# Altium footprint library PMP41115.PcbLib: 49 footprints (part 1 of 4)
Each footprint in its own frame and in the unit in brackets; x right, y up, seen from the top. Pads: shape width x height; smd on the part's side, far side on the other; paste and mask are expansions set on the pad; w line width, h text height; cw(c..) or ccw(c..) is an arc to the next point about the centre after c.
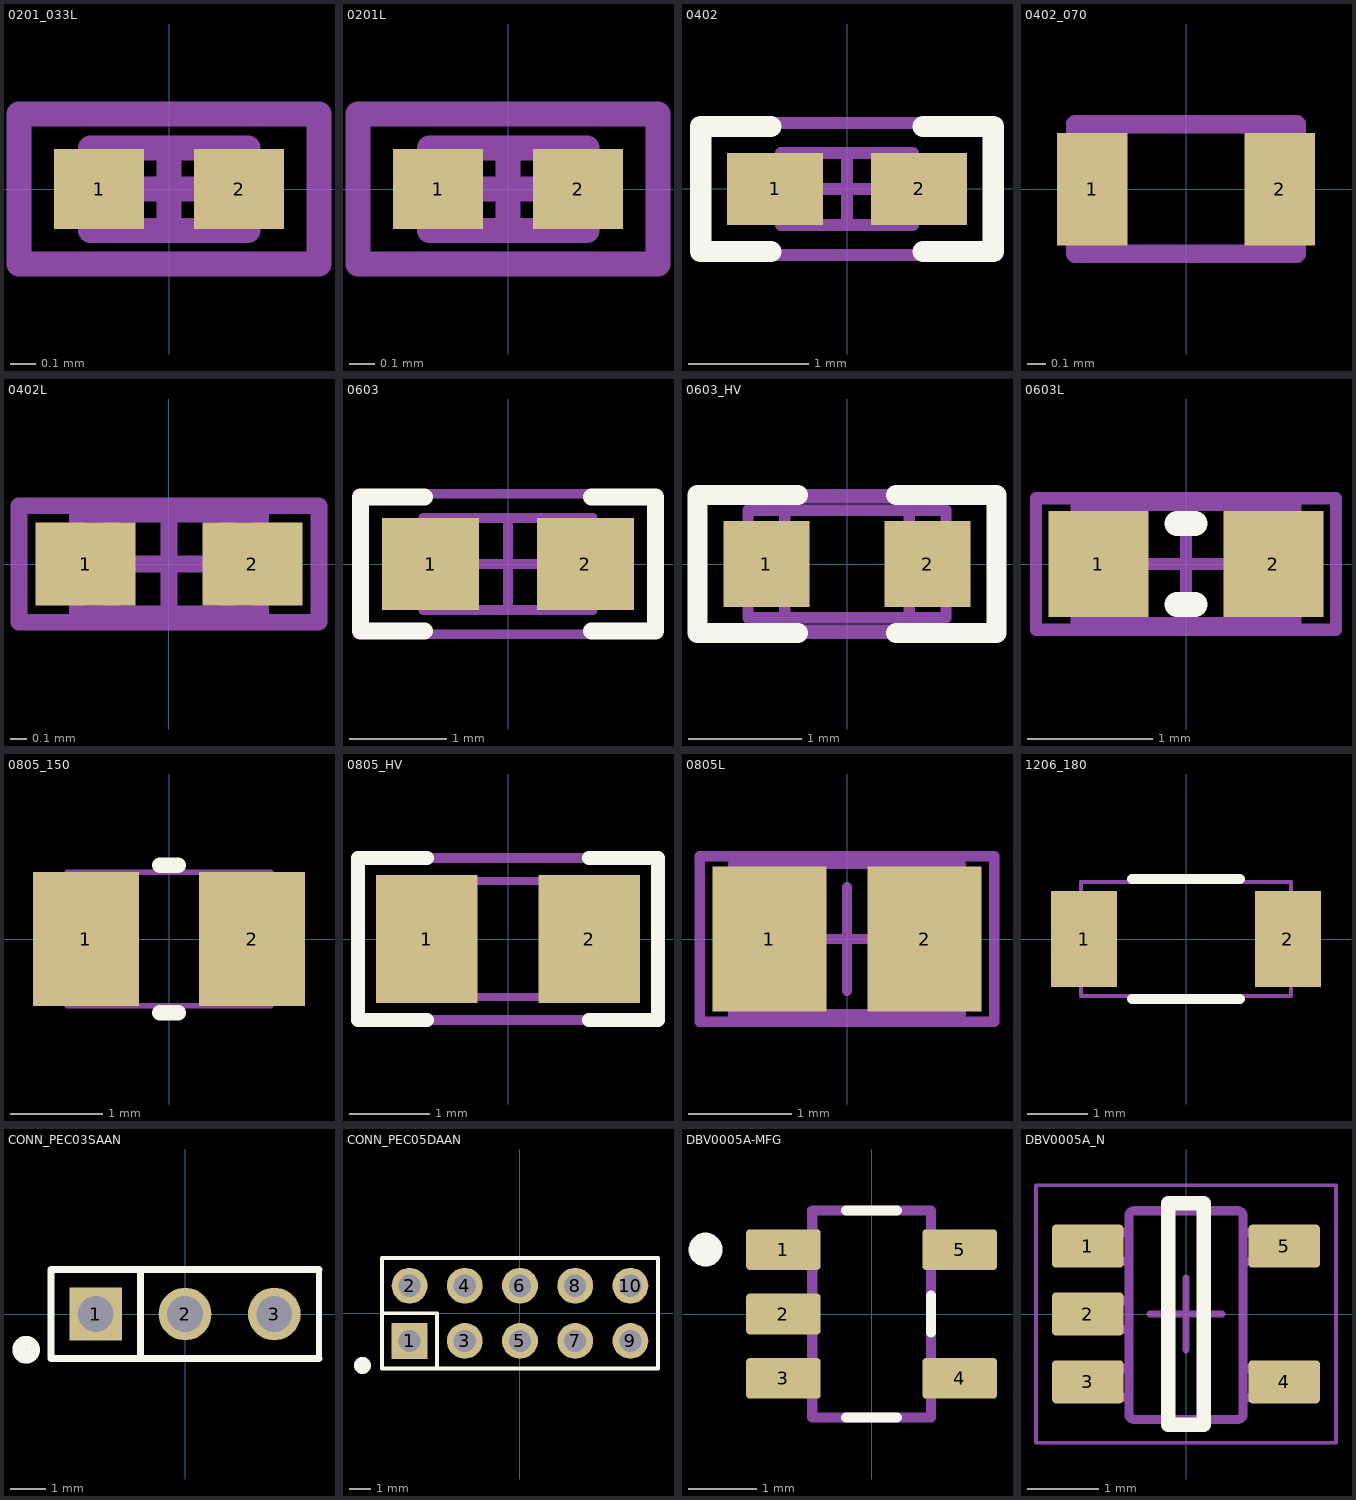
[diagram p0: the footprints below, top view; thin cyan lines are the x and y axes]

## 0201_033L [mm] "0201"
height 0.33
pads (2):
  rect 0.36x0.32 smd mask+0.048: 1(-0.28,0) 2(0.28,0)
Mechanical 5:
  lines w0.1: -0.6,-0.3 -0.6,0.3 0.6,0.3 0.6,-0.3 -0.6,-0.3
  text ".Designator" at -0.5,-0.15 h0.28
Mechanical 13:
  lines w0.1: -0.215,-0.165 -0.215,0.165 ; 0.215,-0.165 0.215,0.165 ; -0.315,-0.165 0.315,-0.165 0.315,0.165 -0.315,0.165 -0.315,-0.165
Mechanical 15:
  lines w0.1: -0.165,0 0.165,0 ; 0,-0.165 0,0.165 ; -0.6,-0.3 0.6,-0.3 0.6,0.3 -0.6,0.3 -0.6,-0.3
3D body: height 0.33, standoff 0, extent 0.216,-0.164 0.314,0.164
3D body: height 0.33, standoff 0, extent -0.214,-0.164 0.214,0.164
3D body: height 0.33, standoff 0, extent -0.314,-0.164 -0.216,0.164

## 0201L [mm] "Data from Kemet datasheet CC101_COM dated 7/28/11"
height 0.26
pads (2):
  rect 0.36x0.32 smd mask+0.048: 1(-0.28,0) 2(0.28,0)
Mechanical 5:
  lines w0.1: -0.6,-0.3 -0.6,0.3 0.6,0.3 0.6,-0.3 -0.6,-0.3
  text ".Designator" at -0.5,-0.15 h0.28
Mechanical 13:
  lines w0.1: -0.215,-0.165 -0.215,0.165 ; 0.215,-0.165 0.215,0.165 ; -0.315,-0.165 0.315,-0.165 0.315,0.165 -0.315,0.165 -0.315,-0.165
Mechanical 15:
  lines w0.1: -0.165,0 0.165,0 ; 0,-0.165 0,0.165 ; -0.6,-0.3 0.6,-0.3 0.6,0.3 -0.6,0.3 -0.6,-0.3
3D body: height 0.26, standoff 0, extent 0.216,-0.164 0.314,0.164
3D body: height 0.26, standoff 0, extent -0.214,-0.164 0.214,0.164
3D body: height 0.26, standoff 0, extent -0.314,-0.164 -0.216,0.164

## 0402 [mm] "0402 from SM-752 data"
height 0.6
pads (2):
  rect 0.8x0.6 smd: 1(-0.6,0) 2(0.6,0)
Top Overlay:
  lines w0.178: -0.635,-0.521 -1.219,-0.521 -1.219,0.521 -0.635,0.521 ; 0.635,-0.521 1.219,-0.521 1.219,0.521 0.635,0.521
Mechanical 5:
  lines w0.1: -1.25,-0.55 1.25,-0.55 1.25,0.55 -1.25,0.55 -1.25,-0.55
  text ".Designator" at -1.117,-0.305 h0.61
Mechanical 13:
  lines w0.1: -0.35,-0.3 -0.35,0.3 ; 0.35,-0.3 0.35,0.3 ; -0.55,-0.3 -0.55,0.3 0.55,0.3 0.55,-0.3 -0.55,-0.3
Mechanical 15:
  lines w0.1: -0.3,0 0.3,0 ; 0,-0.3 0,0.3 ; -1.25,-0.55 -1.25,0.55 1.25,0.55 1.25,-0.55 -1.25,-0.55
3D body: height 0.6, standoff 0, extent -0.549,-0.299 -0.351,0.299
3D body: height 0.6, standoff 0, extent -0.349,-0.299 0.349,0.299
3D body: height 0.6, standoff 0, extent 0.351,-0.299 0.549,0.299

## 0402_070 [mil] "SMD, 2-Leads, Body 1.2x0.7mm, Height 0.7mm"
height 27.56
pads (2):
  rect 15x24 smd: 1(-20,0) 2(20,0)
Mechanical 5:
  lines w3.94: -23.62,-13.78 23.62,-13.78 23.62,13.78 -23.62,13.78 -23.62,-13.78
  text ".Designator" at -21.65,-5.91 h12
3D body: height 27.56, standoff 0, extent -13.78,-13.78 13.78,13.78
3D body: height 27.56, standoff 0, extent -23.62,-13.78 -13.78,13.78
3D body: height 27.56, standoff 0, extent 13.78,-13.78 23.62,13.78

## 0402L [mm] "0402 from SM-752 data"
height 0.6
pads (2):
  rect 0.6x0.5 smd: 1(-0.5,0) 2(0.5,0)
Mechanical 5:
  lines w0.1: -0.9,-0.35 -0.9,0.35 0.9,0.35 0.9,-0.35 -0.9,-0.35
  text ".Designator" at -0.775,-0.225 h0.43
Mechanical 13:
  lines w0.1: -0.35,-0.3 -0.35,0.3 ; 0.35,-0.3 0.35,0.3 ; -0.55,-0.3 0.55,-0.3 0.55,0.3 -0.55,0.3 -0.55,-0.3
Mechanical 15:
  lines w0.1: -0.3,0 0.3,0 ; 0,-0.3 0,0.3 ; -0.9,-0.35 0.9,-0.35 0.9,0.35 -0.9,0.35 -0.9,-0.35
3D body: height 0.6, standoff 0, extent 0.351,-0.299 0.549,0.299
3D body: height 0.6, standoff 0, extent -0.349,-0.299 0.349,0.299
3D body: height 0.6, standoff 0, extent -0.549,-0.299 -0.351,0.299

## 0603 [mm] "0603 from SM-752 data"
height 1
pads (2):
  rect 1x0.95 smd: 1(-0.8,0) 2(0.8,0)
Top Overlay:
  lines w0.178: -0.864,-0.691 -1.524,-0.691 -1.524,0.693 -0.864,0.693 ; 0.864,-0.691 1.524,-0.691 1.524,0.693 0.864,0.693
Mechanical 5:
  lines w0.1: -1.55,-0.725 1.55,-0.725 1.55,0.725 -1.55,0.725 -1.55,-0.725
  text ".Designator" at -1.397,-0.381 h0.76
Mechanical 13:
  lines w0.1: -0.55,-0.475 -0.55,0.475 ; 0.55,-0.475 0.55,0.475 ; -0.875,-0.475 -0.875,0.475 0.875,0.475 0.875,-0.475 -0.875,-0.475
Mechanical 15:
  lines w0.1: -0.475,0 0.475,0 ; 0,-0.475 0,0.475 ; -1.55,-0.725 -1.55,0.725 1.55,0.725 1.55,-0.725 -1.55,-0.725
3D body: height 1, standoff 0, extent 0.551,-0.474 0.874,0.474
3D body: height 1, standoff 0, extent -0.549,-0.474 0.549,0.474
3D body: height 1, standoff 0, extent -0.874,-0.474 -0.551,0.474

## 0603_HV [mil] "Ernesto recommended land pattern.  26 mil between pads."
height 39.37
pads (2):
  rect 30x30 smd: 1(-28,0) 2(28,0)
Top Overlay:
  lines w7: -17,-24 -52,-24 -52,0 -52,24 -17,24 ; 17,-24 52,-24 52,0 52,24 17,24
Mechanical 5:
  lines w5: -52.17,-23.62 52.17,-23.62 52.17,23.62 -52.17,23.62 -52.17,-23.62
  text ".Designator" at -45.82,-12.5 h25
Mechanical 13:
  lines w3.94: -21.65,-18.7 -21.65,18.7 ; 21.65,-18.7 21.65,18.7 ; -34.45,-18.7 34.45,-18.7 34.45,18.7 -34.45,18.7 -34.45,-18.7
3D body: height 39.37, standoff 0, extent -34.43,-18.68 -21.67,18.68
3D body: height 39.37, standoff 0, extent -21.63,-18.68 21.63,18.68
3D body: height 39.37, standoff 0, extent 21.67,-18.68 34.43,18.68

## 0603L [mm] "0603 from SM-752 data"
height 1
pads (2):
  rect 0.8x0.85 smd: 1(-0.7,0) 2(0.7,0)
Top Overlay:
  lines w0.2: -0.071,-0.325 0.071,-0.325 ; -0.071,0.325 0.071,0.325
Mechanical 5:
  lines w0.1: -1.2,-0.525 -1.2,0.525 1.2,0.525 1.2,-0.525 -1.2,-0.525
  text ".Designator" at -1.05,-0.275 h0.56
Mechanical 13:
  lines w0.1: -0.55,-0.475 -0.55,0.475 ; 0.55,-0.475 0.55,0.475 ; -0.875,-0.475 -0.875,0.475 0.875,0.475 0.875,-0.475 -0.875,-0.475
Mechanical 15:
  lines w0.1: -0.475,0 0.475,0 ; 0,-0.475 0,0.475 ; -1.2,-0.525 1.2,-0.525 1.2,0.525 -1.2,0.525 -1.2,-0.525
3D body: height 1, standoff 0, extent 0.551,-0.474 0.874,0.474
3D body: height 1, standoff 0, extent -0.549,-0.474 0.549,0.474
3D body: height 1, standoff 0, extent -0.874,-0.474 -0.551,0.474

## 0805_150 [mm] "0805 / 1.5 mm height"
height 1.5
pads (2):
  rect 1.15x1.45 smd: 1(-0.9,0) 2(0.9,0)
Top Overlay:
  lines w0.17: -0.1,-0.8 0.1,-0.8 ; -0.1,0.8 0.1,0.8
Mechanical 5:
  lines w0.06: -1.1,-0.725 -1.1,0.725 1.1,0.725 1.1,-0.725 -1.1,-0.725
  text ".Designator" at -0.975,-0.3 h0.53
3D body: height 1.5, standoff 0, extent 0.501,-0.724 1.099,0.724
3D body: height 1.5, standoff 0, extent -0.499,-0.724 0.5,0.725
3D body: height 1.5, standoff 0, extent -1.099,-0.724 -0.501,0.724

## 0805_HV [mil] "0805 with 30mil clearance between pads"
height 57.09
pads (2):
  rect 50x63 smd: 1(-40,0) 2(40,0)
Top Overlay:
  lines w7: -40,-40 -74,-40 -74,0 -74,40 -40,40 ; 40,-40 74,-40 74,0 74,40 40,40
Mechanical 5:
  lines w5: -74,-40 74,-40 74,40 -74,40 -74,-40
  text ".Designator" at -64,-17 h35
Mechanical 13:
  lines w3.94: -25.59,-28.54 -25.59,28.54 ; 25.59,-28.54 25.59,28.54 ; -43.31,-28.54 43.31,-28.54 43.31,28.54 -43.31,28.54 -43.31,-28.54
3D body: height 57.09, standoff 0, extent -43.29,-28.52 -25.61,28.52
3D body: height 57.09, standoff 0, extent -25.57,-28.52 25.57,28.52
3D body: height 57.09, standoff 0, extent 25.61,-28.52 43.29,28.52

## 0805L [mm] "0805 from SM-752 data"
height 1.45
pads (2):
  rect 1.1x1.4 smd: 1(-0.75,0) 2(0.75,0)
Mechanical 5:
  lines w0.1: -1.425,-0.8 1.425,-0.8 1.425,0.8 -1.425,0.8 -1.425,-0.8
  text ".Designator" at -1.2,-0.325 h0.64
Mechanical 13:
  lines w0.1: -0.65,-0.725 -0.65,0.725 ; 0.65,-0.725 0.65,0.725 ; -1.1,-0.725 -1.1,0.725 1.1,0.725 1.1,-0.725 -1.1,-0.725
Mechanical 15:
  lines w0.1: -0.5,0 0.5,0 ; 0,-0.5 0,0.5 ; -1.425,-0.8 -1.425,0.8 1.425,0.8 1.425,-0.8 -1.425,-0.8
3D body: height 1.45, standoff 0, extent 0.651,-0.724 1.099,0.724
3D body: height 1.45, standoff 0, extent -0.649,-0.724 0.649,0.724
3D body: height 1.45, standoff 0, extent -1.099,-0.724 -0.651,0.724

## 1206_180 [mm] "1206_180"
height 1.8
pads (2):
  rect 1.1x1.6 smd: 1(-1.7,0) 2(1.7,0)
Top Overlay:
  lines w0.17: -0.9,-1 0.9,-1 ; -0.9,1 0.9,1
Mechanical 5:
  lines w0.07: -1.75,-0.95 1.75,-0.95 1.75,0.95 -1.75,0.95 -1.75,-0.95
  text ".Designator" at -1.5,-0.4 h0.81
3D body: height 1.8, standoff 0, extent -1.749,-0.949 -1.301,0.949
3D body: height 1.8, standoff 0, extent -1.299,-0.949 1.299,0.949
3D body: height 1.8, standoff 0, extent 1.301,-0.949 1.749,0.949

## CONN_PEC03SAAN [mm] "SULLINS"
height 8.38
pads (3):
  rect 1.5x1.5 hole 1.016: 1(-2.54,0)
  round 1.5 hole 1.016: 2(0,0) 3(2.54,0)
Top Overlay:
  circle w0.381: c-4.521,-1.016 r0.203
  lines w0.178: 3.81,-1.27 3.81,0.254 3.81,1.27
  lines w0.203: -1.27,1.27 -1.27,-1.27 ; 3.81,-1.27 -1.27,-1.27 ; 3.81,1.27 -3.81,1.27 -3.81,-1.27 -1.27,-1.27
Mechanical 5:
  rectangle: -3.048,-0.508 -2.032,0.508
  lines w0.127: -3.81,-1.27 -3.81,1.27 3.81,1.27 3.81,-1.27 -3.81,-1.27
  text ".Designator" at -1.524,-0.254 h0.76
3D body: height 8.38, standoff -3.05, extent 2.236,-0.304 2.844,0.304
3D body: height 8.38, standoff -3.05, extent -0.304,-0.304 0.304,0.304
3D body: height 8.38, standoff -3.05, extent -2.844,-0.304 -2.236,0.304
3D body: height 2.54, standoff 0, extent -3.835,-1.295 3.835,1.295

## CONN_PEC05DAAN [mm] "SULLINS"
height 8.382
pads (10):
  rect 1.65x1.65 hole 1.016 mask+0: 1(-5.08,-1.27)
  round 1.65 hole 1.016 mask+0: 2(-5.08,1.27) 3(-2.54,-1.27) 4(-2.54,1.27) 5(0,-1.27) 6(0,1.27) 7(2.54,-1.27) 8(2.54,1.27) 9(5.08,-1.27) 10(5.08,1.27)
Top Overlay:
  circle w0.381: c-7.25,-2.4 r0.203
  lines w0.178: -6.35,0 -3.81,0 -3.81,-2.54 ; -6.35,-2.54 -6.35,2.54 6.35,2.54 6.35,-2.54 -6.35,-2.54
Mechanical 5:
  rectangle: -5.588,-1.778 -4.572,-0.762
  lines w0.076: -6.35,-2.54 -6.35,2.54 6.35,2.54 6.35,-2.54 -6.35,-2.54
  lines w0.127: -6.35,-2.54 6.35,-2.54 6.35,2.54 -6.35,2.54 -6.35,-2.54
  text ".Designator" at -1.778,-0.508 h1.02
3D body: height 2.54, standoff 0, extent -6.349,-2.539 6.349,2.539
3D body: height 8.38, standoff -3.05, extent 4.763,0.953 5.398,1.588
3D body: height 8.38, standoff -3.05, extent 4.763,-1.587 5.398,-0.952
3D body: height 8.38, standoff -3.05, extent 2.223,0.953 2.858,1.588
3D body: height 8.38, standoff -3.05, extent 2.223,-1.587 2.858,-0.952
3D body: height 8.38, standoff -3.05, extent -0.317,0.953 0.318,1.588
3D body: height 8.38, standoff -3.05, extent -0.317,-1.587 0.318,-0.952
3D body: height 8.38, standoff -3.05, extent -2.857,-1.587 -2.222,-0.952
3D body: height 8.38, standoff -3.05, extent -2.857,0.953 -2.222,1.588
3D body: height 8.38, standoff -3.05, extent -5.397,0.953 -4.762,1.588
3D body: height 8.38, standoff -3.05, extent -5.397,-1.587 -4.762,-0.952

## DBV0005A-MFG [mm]
pads (5):
  rrect17% 1.1x0.6 smd paste+0 mask+0: 1(-1.3,0.95) 2(-1.3,0) 3(-1.3,-0.95) 4(1.3,-0.95) 5(1.3,0.95)
Top Overlay:
  circle w0.25: c-2.45,0.95 r0.125
  lines w0.15: -0.375,-1.525 0.375,-1.525 ; -0.375,1.525 0.375,1.525 ; 0.875,-0.275 0.875,0.275
Mechanical 5:
  lines w0.15: -0.875,-1.525 -0.875,1.525 0.875,1.525 0.875,-1.525 -0.875,-1.525
  text ".Designator" at 0.05,0.217 h0.5
3D body "IC_TPS7A2450DBVR_SOT23-5.STEP": height 0.25, standoff 0, extent -1.95,-1.775 1.95,1.775

## DBV0005A_N [mm] "SOT23, 5-Leads, Body 2.9x1.6mm, Pitch 0.95mm, Lead Span 2.8mm, IPC Medium Density"
height 1.45
pads (5):
  rrect17% 1x0.6 smd: 1(-1.375,0.95) 2(-1.375,0) 3(-1.375,-0.95) 4(1.375,-0.95) 5(1.375,0.95)
Top Overlay:
  lines w0.2: -0.25,-1.55 0.25,-1.55 0.25,1.55 -0.25,1.55 -0.25,-1.55
Mechanical 5:
  lines w0.127: -0.801,1.371 cw(c-0.725,1.37) -0.725,1.446 ; -0.801,1.37 -0.801,-1.399 -0.801,-1.4 ccw(c-0.725,-1.399) -0.725,-1.475 ; -0.801,1.37 -0.801,1.371 ; -0.725,-1.475 -0.725,-1.475 ; -0.725,-1.475 0.723,-1.475 0.724,-1.475 ccw(c0.723,-1.399) 0.799,-1.4 0.799,-1.399 0.799,1.37 ; -0.725,1.446 0.723,1.446 0.724,1.446 cw(c0.723,1.37) 0.799,1.371 ; -0.725,1.446 -0.725,1.446 ; 0.799,1.37 0.799,1.371 ; -1.423,-1.167 -1.199,-1.167 -1.105,-1.167 -1.088,-1.167 -0.835,-1.167 -0.801,-1.167 -0.801,-0.767 -0.835,-0.767 -1.088,-0.767 -1.105,-0.767 -1.199,-0.767 -1.423,-0.767 -1.423,-1.167 ; -1.423,-0.215 -1.199,-0.215 -1.105,-0.215 -1.088,-0.215 -0.835,-0.215 -0.801,-0.215 -0.801,0.186 -0.835,0.186 -1.088,0.186 -1.105,0.186 -1.199,0.186 -1.423,0.186 -1.423,-0.215 ; -1.423,0.738 -1.199,0.738 -1.105,0.738 -1.088,0.738 -0.835,0.738 -0.801,0.738 -0.801,1.138 -0.835,1.138 -1.088,1.138 -1.105,1.138 -1.199,1.138 -1.423,1.138 -1.423,0.738 ; 0.799,-1.167 0.799,-0.767 0.834,-0.767 1.087,-0.767 1.103,-0.767 1.198,-0.767 1.422,-0.767 1.422,-1.167 1.198,-1.167 1.103,-1.167 1.087,-1.167 0.834,-1.167 0.799,-1.167 ; 0.799,0.738 0.799,1.138 0.834,1.138 1.087,1.138 1.103,1.138 1.198,1.138 1.422,1.138 1.422,0.738 1.198,0.738 1.103,0.738 1.087,0.738 0.834,0.738 0.799,0.738
  text ".Designator" at -0.25,0.95 h0.51
Mechanical 15:
  lines w0.05: -2.1,-1.8 2.1,-1.8 2.1,1.8 -2.1,1.8 -2.1,-1.8
  lines w0.1: -0.5,0 0.5,0 ; 0,-0.5 0,0.5
3D body "DBV0005A.stp": height 1.09, standoff 0, extent -1.422,-1.461 1.423,1.46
